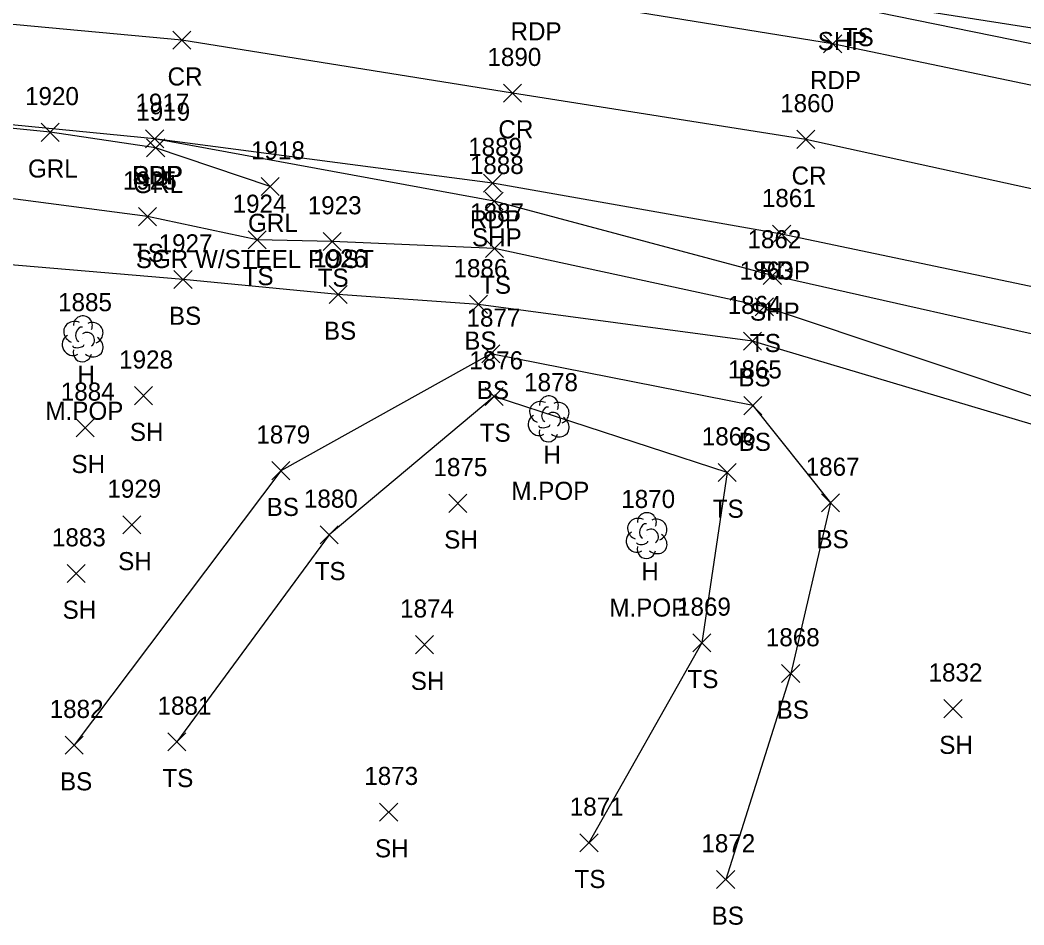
# Model space of a CAD drawing. Extents: x 1497084 to 1499861, y 734741 to 735567.
# Drawn here: x 1499630.8 to 1499741.8, y 735356.1 to 735456.1 of the extents above; entities that cross this region are included whole.
import ezdxf

# ---------------------------------------------------------------- set-up
doc = ezdxf.new("R2010")
doc.units = 0
for name, color, linetype in [('L_A', 7, 'Continuous'), ('L_C', 7, 'Continuous'), ('L_I', 7, 'Continuous'), ('L_TIC', 7, 'Continuous'), ('LELB', 7, 'Continuous'), ('LTD', 7, 'Continuous'), ('P_A', 7, 'Continuous'), ('P_I', 7, 'Continuous'), ('P_TIC', 7, 'Continuous'), ('PET', 7, 'Continuous'), ('PRC', 7, 'Continuous'), ('PSP', 7, 'Continuous'), ('R_A', 7, 'Continuous'), ('R_C', 7, 'Continuous'), ('R_I', 7, 'Continuous'), ('R_TIC', 7, 'Continuous'), ('RGR', 7, 'Continuous')]:
    doc.layers.add(name, color=color, linetype=linetype)

msp = doc.modelspace()

# ---------------------------------------------------------------- linework, layer by layer
at = {"layer": 'L_TIC'}
for points in [[(1499643.89, 735433.35), (1499645.89, 735435.35)], [(1499645.89, 735433.35), (1499643.89, 735435.35)], [(1499656.01, 735430.78), (1499658.01, 735432.78)], [(1499658.01, 735430.78), (1499656.01, 735432.78)], [(1499664.3, 735430.61), (1499666.3, 735432.61)], [(1499666.3, 735430.61), (1499664.3, 735432.61)], [(1499682.25, 735429.83), (1499684.25, 735431.83)], [(1499684.25, 735429.83), (1499682.25, 735431.83)], [(1499647.83, 735426.4), (1499649.83, 735428.4)], [(1499649.83, 735426.4), (1499647.83, 735428.4)], [(1499664.96, 735424.75), (1499666.96, 735426.75)], [(1499666.96, 735424.75), (1499664.96, 735426.75)], [(1499680.47, 735423.66), (1499682.47, 735425.66)], [(1499682.47, 735423.66), (1499680.47, 735425.66)], [(1499712.07, 735423.39), (1499714.07, 735425.39)], [(1499714.07, 735423.39), (1499712.07, 735425.39)], [(1499710.76, 735419.6), (1499712.76, 735421.6)], [(1499712.76, 735419.6), (1499710.76, 735421.6)], [(1499681.85, 735418.2), (1499683.85, 735420.2)], [(1499683.85, 735418.2), (1499681.85, 735420.2)], [(1499643.47, 735413.57), (1499645.47, 735415.57)], [(1499645.47, 735413.57), (1499643.47, 735415.57)], [(1499682.21, 735413.48), (1499684.21, 735415.48)], [(1499684.21, 735413.48), (1499682.21, 735415.48)], [(1499710.79, 735412.47), (1499712.79, 735414.47)], [(1499712.79, 735412.47), (1499710.79, 735414.47)], [(1499710.79, 735412.47), (1499712.79, 735414.47)], [(1499712.79, 735412.47), (1499710.79, 735414.47)], [(1499637.01, 735410.02), (1499639.01, 735412.02)], [(1499639.01, 735410.02), (1499637.01, 735412.02)], [(1499658.63, 735405.28), (1499660.63, 735407.28)], [(1499660.63, 735405.28), (1499658.63, 735407.28)], [(1499707.96, 735405.08), (1499709.96, 735407.08)], [(1499709.96, 735405.08), (1499707.96, 735407.08)], [(1499707.96, 735405.08), (1499709.96, 735407.08)], [(1499709.96, 735405.08), (1499707.96, 735407.08)], [(1499678.2, 735401.68), (1499680.2, 735403.68)], [(1499680.2, 735401.68), (1499678.2, 735403.68)], [(1499719.39, 735401.72), (1499721.39, 735403.72)], [(1499721.39, 735401.72), (1499719.39, 735403.72)], [(1499642.17, 735399.29), (1499644.17, 735401.29)], [(1499644.17, 735399.29), (1499642.17, 735401.29)], [(1499663.97, 735398.19), (1499665.97, 735400.19)], [(1499665.97, 735398.19), (1499663.97, 735400.19)], [(1499636.03, 735393.92), (1499638.03, 735395.92)], [(1499638.03, 735393.92), (1499636.03, 735395.92)], [(1499674.51, 735386.06), (1499676.51, 735388.06)], [(1499676.51, 735386.06), (1499674.51, 735388.06)], [(1499705.17, 735386.26), (1499707.17, 735388.26)], [(1499707.17, 735386.26), (1499705.17, 735388.26)], [(1499714.98, 735382.88), (1499716.98, 735384.88)], [(1499716.98, 735382.88), (1499714.98, 735384.88)], [(1499732.92, 735378.99), (1499734.92, 735380.99)], [(1499734.92, 735378.99), (1499732.92, 735380.99)], [(1499635.79, 735374.96), (1499637.79, 735376.96)], [(1499637.79, 735374.96), (1499635.79, 735376.96)], [(1499647.14, 735375.32), (1499649.14, 735377.32)], [(1499649.14, 735375.32), (1499647.14, 735377.32)], [(1499670.55, 735367.56), (1499672.55, 735369.56)], [(1499672.55, 735367.56), (1499670.55, 735369.56)], [(1499692.69, 735364.17), (1499694.69, 735366.17)], [(1499694.69, 735364.17), (1499692.69, 735366.17)], [(1499707.8, 735360.12), (1499709.8, 735362.12)], [(1499709.8, 735360.12), (1499707.8, 735362.12)]]:
    msp.add_lwpolyline(points, dxfattribs=at)
at = {"layer": 'LELB'}
for points in [[(1499770.6, 735459.37), (1499767.32, 735451.4), (1499753.27, 735453.51), (1499723.33, 735458.19), (1499688.04, 735465.79), (1499662, 735476.73), (1499649.94, 735471.98), (1499600.23, 735477.81), (1499596.97, 735472.37)], [(1499839.85, 735392.86), (1499780.55, 735401.53), (1499747.75, 735409.88), (1499711.76, 735420.6), (1499681.47, 735424.66), (1499665.96, 735425.75), (1499648.83, 735427.4), (1499598.57, 735431.68), (1499589.95, 735436.64), (1499584.82, 735440.49), (1499583.81, 735444.46), (1499585.42, 735446.56), (1499592.69, 735446.66)], [(1499841.23, 735396.64), (1499780.79, 735407.69), (1499746.05, 735413.36), (1499713.07, 735424.39), (1499683.25, 735430.83), (1499665.3, 735431.61), (1499657.01, 735431.78), (1499644.89, 735434.35), (1499602.81, 735439.91), (1499596.15, 735442.52), (1499594.16, 735445.59)], [(1499711.79, 735413.47), (1499682.85, 735419.2), (1499659.63, 735406.28), (1499636.79, 735375.96)], [(1499708.96, 735406.08), (1499683.21, 735414.48), (1499664.97, 735399.19), (1499648.14, 735376.32)], [(1499711.79, 735413.47), (1499720.39, 735402.72), (1499715.98, 735383.88), (1499708.8, 735361.12)], [(1499708.96, 735406.08), (1499706.17, 735387.26), (1499693.69, 735365.17)]]:
    msp.add_lwpolyline(points, dxfattribs=at)
at = {"layer": 'LTD'}
for p, q in [((1499637.72, 735420.9), (1499637.72, 735420.9)), ((1499637.72, 735420.9), (1499637.72, 735420.9)), ((1499689.22, 735412.06), (1499689.22, 735412.06)), ((1499689.22, 735412.06), (1499689.22, 735412.06)), ((1499700.04, 735399.16), (1499700.04, 735399.16)), ((1499700.04, 735399.16), (1499700.04, 735399.16))]:
    msp.add_line(p, q, dxfattribs=at)
for centre in [(1499637.76, 735422.33), (1499689.26, 735413.49), (1499700.09, 735400.59)]:
    msp.add_arc(centre, 1.05, 335.5272, 180.9563, dxfattribs=at)
for centre, major_axis, ratio, start_param, end_param in [((1499636.93, 735421.57), (1.21, -0.51), 0.895232, 1.570796, 4.712389), ((1499637.51, 735421.36), (-0.208, -0.792), 0.645439, 3.141593, 6.283185), ((1499638.76, 735421.48), (-1.14, -0.48), 0.949671, 1.570796, 4.712389), ((1499636.63, 735420.19), (0.58, -1.04), 0.959034, 3.141593, 6.283185), ((1499638.22, 735420.73), (-0.5, 0.667), 0.989748, 3.141593, 6.283185), ((1499638.72, 735420.07), (-1.09, 0.79), 0.841452, 1.570796, 4.712389), ((1499637.72, 735419.4), (0.26, 1.06), 0.942809, 1.570796, 4.712389), ((1499637.26, 735420.15), (-0.625, -0.083), 0.423636, 0, 3.141593), ((1499688.42, 735412.72), (1.21, -0.51), 0.895232, 1.570796, 4.712389), ((1499689.01, 735412.52), (-0.208, -0.792), 0.645439, 3.141593, 6.283185), ((1499690.26, 735412.64), (-1.14, -0.48), 0.949671, 1.570796, 4.712389), ((1499688.13, 735411.35), (0.58, -1.04), 0.959034, 3.141593, 6.283185), ((1499689.72, 735411.89), (-0.5, 0.667), 0.989748, 3.141593, 6.283185), ((1499690.22, 735411.23), (-1.09, 0.79), 0.841452, 1.570796, 4.712389), ((1499689.22, 735410.56), (0.26, 1.06), 0.942809, 1.570796, 4.712389), ((1499688.76, 735411.31), (-0.625, -0.083), 0.423636, 0, 3.141593), ((1499699.25, 735399.82), (1.21, -0.51), 0.895232, 1.570796, 4.712389), ((1499701.08, 735399.74), (-1.14, -0.48), 0.949671, 1.570796, 4.712389), ((1499699.83, 735399.62), (-0.208, -0.792), 0.645439, 3.141593, 6.283185), ((1499700.54, 735398.99), (-0.5, 0.667), 0.989748, 3.141593, 6.283185), ((1499698.96, 735398.45), (0.58, -1.04), 0.959034, 3.141593, 6.283185), ((1499701.04, 735398.33), (-1.09, 0.79), 0.841452, 1.570796, 4.712389), ((1499700.04, 735397.66), (0.26, 1.06), 0.942809, 1.570796, 4.712389), ((1499699.58, 735398.41), (-0.625, -0.083), 0.423636, 0, 3.141593)]:
    msp.add_ellipse(centre, major_axis=major_axis, ratio=ratio, start_param=start_param, end_param=end_param, dxfattribs=at)
at = {"layer": 'P_TIC'}
for points in [[(1499647.69, 735452.84), (1499649.69, 735454.84)], [(1499649.69, 735452.84), (1499647.69, 735454.84)], [(1499719.62, 735452.44), (1499721.62, 735454.44)], [(1499721.62, 735452.44), (1499719.62, 735454.44)], [(1499684.25, 735447), (1499686.25, 735449)], [(1499686.25, 735447), (1499684.25, 735449)], [(1499644.69, 735441.94), (1499646.69, 735443.94)], [(1499646.69, 735441.94), (1499644.69, 735443.94)], [(1499644.69, 735441.94), (1499646.69, 735443.94)], [(1499646.69, 735441.94), (1499644.69, 735443.94)], [(1499716.65, 735441.89), (1499718.65, 735443.89)], [(1499718.65, 735441.89), (1499716.65, 735443.89)], [(1499682.04, 735437.06), (1499684.04, 735439.06)], [(1499684.04, 735437.06), (1499682.04, 735439.06)], [(1499682.22, 735435.06), (1499684.22, 735437.06)], [(1499684.22, 735435.06), (1499682.22, 735437.06)], [(1499713.98, 735431.41), (1499715.98, 735433.41)], [(1499715.98, 735431.41), (1499713.98, 735433.41)], [(1499712.95, 735426.86), (1499714.95, 735428.86)], [(1499714.95, 735426.86), (1499712.95, 735428.86)]]:
    msp.add_lwpolyline(points, dxfattribs=at)
at = {"layer": 'PET'}
for points in [[(1499842.35, 735402.93), (1499782.68, 735418.08), (1499750.41, 735424.99), (1499714.98, 735432.41), (1499683.04, 735438.06), (1499645.69, 735442.94), (1499594.85, 735447.92), (1499595.43, 735458.81), (1499596.08, 735469.99)], [(1499846.49, 735425.23), (1499785.87, 735440.03), (1499753.42, 735446.61), (1499720.62, 735453.44), (1499687.53, 735458.83), (1499650.76, 735464.5), (1499635.87, 735466.46), (1499596.08, 735469.99)]]:
    msp.add_lwpolyline(points, dxfattribs=at)
at = {"layer": 'PRC'}
msp.add_lwpolyline([(1499843.89, 735414.07), (1499783.91, 735429.16), (1499752.36, 735435.28), (1499717.65, 735442.89), (1499685.25, 735448), (1499648.69, 735453.84), (1499595.43, 735458.81)], dxfattribs=at)
at = {"layer": 'PSP'}
for points in [[(1499847.6, 735429.73), (1499789.27, 735443.96), (1499769.13, 735448.7), (1499753.08, 735451.31), (1499721.43, 735457.75), (1499687.71, 735461.33), (1499651.84, 735466.26), (1499635.87, 735466.46)], [(1499842.15, 735398.82), (1499781.91, 735413.58), (1499749.27, 735419.91), (1499713.95, 735427.86), (1499683.22, 735436.06), (1499645.69, 735442.94)]]:
    msp.add_lwpolyline(points, dxfattribs=at)
at = {"layer": 'R_TIC'}
for points in [[(1499633.15, 735442.67), (1499635.15, 735444.67)], [(1499635.15, 735442.67), (1499633.15, 735444.67)], [(1499644.8, 735440.95), (1499646.8, 735442.95)], [(1499646.8, 735440.95), (1499644.8, 735442.95)], [(1499657.47, 735436.67), (1499659.47, 735438.67)], [(1499659.47, 735436.67), (1499657.47, 735438.67)]]:
    msp.add_lwpolyline(points, dxfattribs=at)
at = {"layer": 'RGR'}
msp.add_lwpolyline([(1499658.47, 735437.67), (1499645.8, 735441.95), (1499634.15, 735443.67), (1499594.81, 735447.64)], dxfattribs=at)

# ---------------------------------------------------------------- texts
at = {"layer": 'L_A'}
for s, p in [('TS', (1499721.74, 735453.19)), ('TS', (1499643.29, 735429.35)), ('TS', (1499655.42, 735426.78)), ('TS', (1499663.71, 735426.61)), ('TS', (1499681.66, 735425.83)), ('BS', (1499647.27, 735422.4)), ('BS', (1499664.4, 735420.75)), ('BS', (1499679.91, 735419.66)), ('TS', (1499711.48, 735419.39)), ('H', (1499637.15, 735415.9)), ('BS', (1499710.2, 735415.6)), ('BS', (1499681.29, 735414.2)), ('SH', (1499642.95, 735409.57)), ('TS', (1499681.62, 735409.48)), ('BS', (1499710.23, 735408.47)), ('BS', (1499710.23, 735408.47)), ('H', (1499688.65, 735407.06)), ('SH', (1499636.5, 735406.02)), ('BS', (1499658.07, 735401.28)), ('TS', (1499707.37, 735401.08)), ('TS', (1499707.37, 735401.08)), ('SH', (1499677.69, 735397.68)), ('BS', (1499718.83, 735397.72)), ('SH', (1499641.66, 735395.29)), ('TS', (1499663.38, 735394.19)), ('H', (1499699.47, 735394.16)), ('SH', (1499635.52, 735389.92)), ('SH', (1499674, 735382.06)), ('TS', (1499704.58, 735382.26)), ('BS', (1499714.43, 735378.88)), ('SH', (1499732.4, 735374.99)), ('TS', (1499646.55, 735371.32)), ('BS', (1499635.23, 735370.96)), ('SH', (1499670.04, 735363.56)), ('TS', (1499692.1, 735360.17)), ('BS', (1499707.24, 735356.12))]:
    msp.add_text(s, height=2, dxfattribs=at).set_placement(p)
at = {"layer": 'L_C'}
for p in [(1499633.62, 735411.9), (1499685.11, 735403.06), (1499695.94, 735390.16)]:
    msp.add_text('M.POP', height=2, dxfattribs=at).set_placement(p)
at = {"layer": 'L_I'}
for s, p in [('1925', (1499642.19, 735437.35)), ('1924', (1499654.31, 735434.78)), ('1923', (1499662.61, 735434.61)), ('1887', (1499680.56, 735433.83)), ('1927', (1499646.13, 735430.4)), ('1926', (1499663.21, 735428.75)), ('1886', (1499678.72, 735427.66)), ('1863', (1499710.33, 735427.39)), ('1885', (1499635.02, 735423.9)), ('1864', (1499709.02, 735423.6)), ('1877', (1499680.16, 735422.2)), ('1928', (1499641.77, 735417.57)), ('1876', (1499680.46, 735417.48)), ('1865', (1499709.05, 735416.47)), ('1865', (1499709.05, 735416.47)), ('1878', (1499686.52, 735415.06)), ('1884', (1499635.32, 735414.02)), ('1879', (1499656.93, 735409.28)), ('1866', (1499706.16, 735409.08)), ('1866', (1499706.16, 735409.08)), ('1875', (1499676.51, 735405.68)), ('1867', (1499717.64, 735405.72)), ('1929', (1499640.47, 735403.29)), ('1880', (1499662.19, 735402.19)), ('1870', (1499697.26, 735402.16)), ('1883', (1499634.34, 735397.92)), ('1874', (1499672.82, 735390.06)), ('1869', (1499703.42, 735390.26)), ('1868', (1499713.24, 735386.88)), ('1832', (1499731.22, 735382.99)), ('1882', (1499634.09, 735378.96)), ('1881', (1499646.01, 735379.32)), ('1873', (1499668.86, 735371.56)), ('1871', (1499691.57, 735368.17)), ('1872', (1499706.11, 735364.12))]:
    msp.add_text(s, height=2, dxfattribs=at).set_placement(p)
at = {"layer": 'P_A'}
for s, p in [('RDP', (1499685.02, 735453.83)), ('SHP', (1499718.97, 735452.75)), ('CR', (1499647.12, 735448.84)), ('RDP', (1499718.11, 735448.44)), ('CR', (1499683.68, 735443)), ('SHP', (1499643.23, 735437.94)), ('RDP', (1499643.18, 735437.94)), ('CR', (1499716.08, 735437.89)), ('RDP', (1499680.53, 735433.06)), ('SHP', (1499680.76, 735431.06)), ('RDP', (1499712.47, 735427.41)), ('SHP', (1499711.48, 735422.86))]:
    msp.add_text(s, height=2, dxfattribs=at).set_placement(p)
at = {"layer": 'P_I'}
for s, p in [('1890', (1499682.47, 735451)), ('1917', (1499643.57, 735445.94)), ('1917', (1499643.57, 735445.94)), ('1860', (1499714.82, 735445.89)), ('1889', (1499680.34, 735441.06)), ('1888', (1499680.53, 735439.06)), ('1861', (1499712.8, 735435.41)), ('1862', (1499711.21, 735430.86))]:
    msp.add_text(s, height=2, dxfattribs=at).set_placement(p)
at = {"layer": 'R_A'}
for p in [(1499631.69, 735438.67), (1499643.34, 735436.95), (1499656.01, 735432.67)]:
    msp.add_text('GRL', height=2, dxfattribs=at).set_placement(p)
at = {"layer": 'R_C'}
msp.add_text('SGR W/STEEL POST', height=2, dxfattribs=at).set_placement((1499643.61, 735428.67))
at = {"layer": 'R_I'}
for s, p in [('1920', (1499631.37, 735446.67)), ('1919', (1499643.66, 735444.95)), ('1918', (1499656.34, 735440.67))]:
    msp.add_text(s, height=2, dxfattribs=at).set_placement(p)

doc.saveas('drawing.dxf')
